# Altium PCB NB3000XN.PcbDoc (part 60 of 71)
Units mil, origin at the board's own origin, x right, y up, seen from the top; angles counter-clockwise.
Board outline 9527.56 x 6929.77 mil, 6 copper layers (Top Layer, GND+SHIELD, MidLayer1, MidLayer2, P2 - 3V3+5V0, Bottom Layer), stack 62.375 mil thick; 832 components, 1027 nets, 4655 pads, 4981 vias.
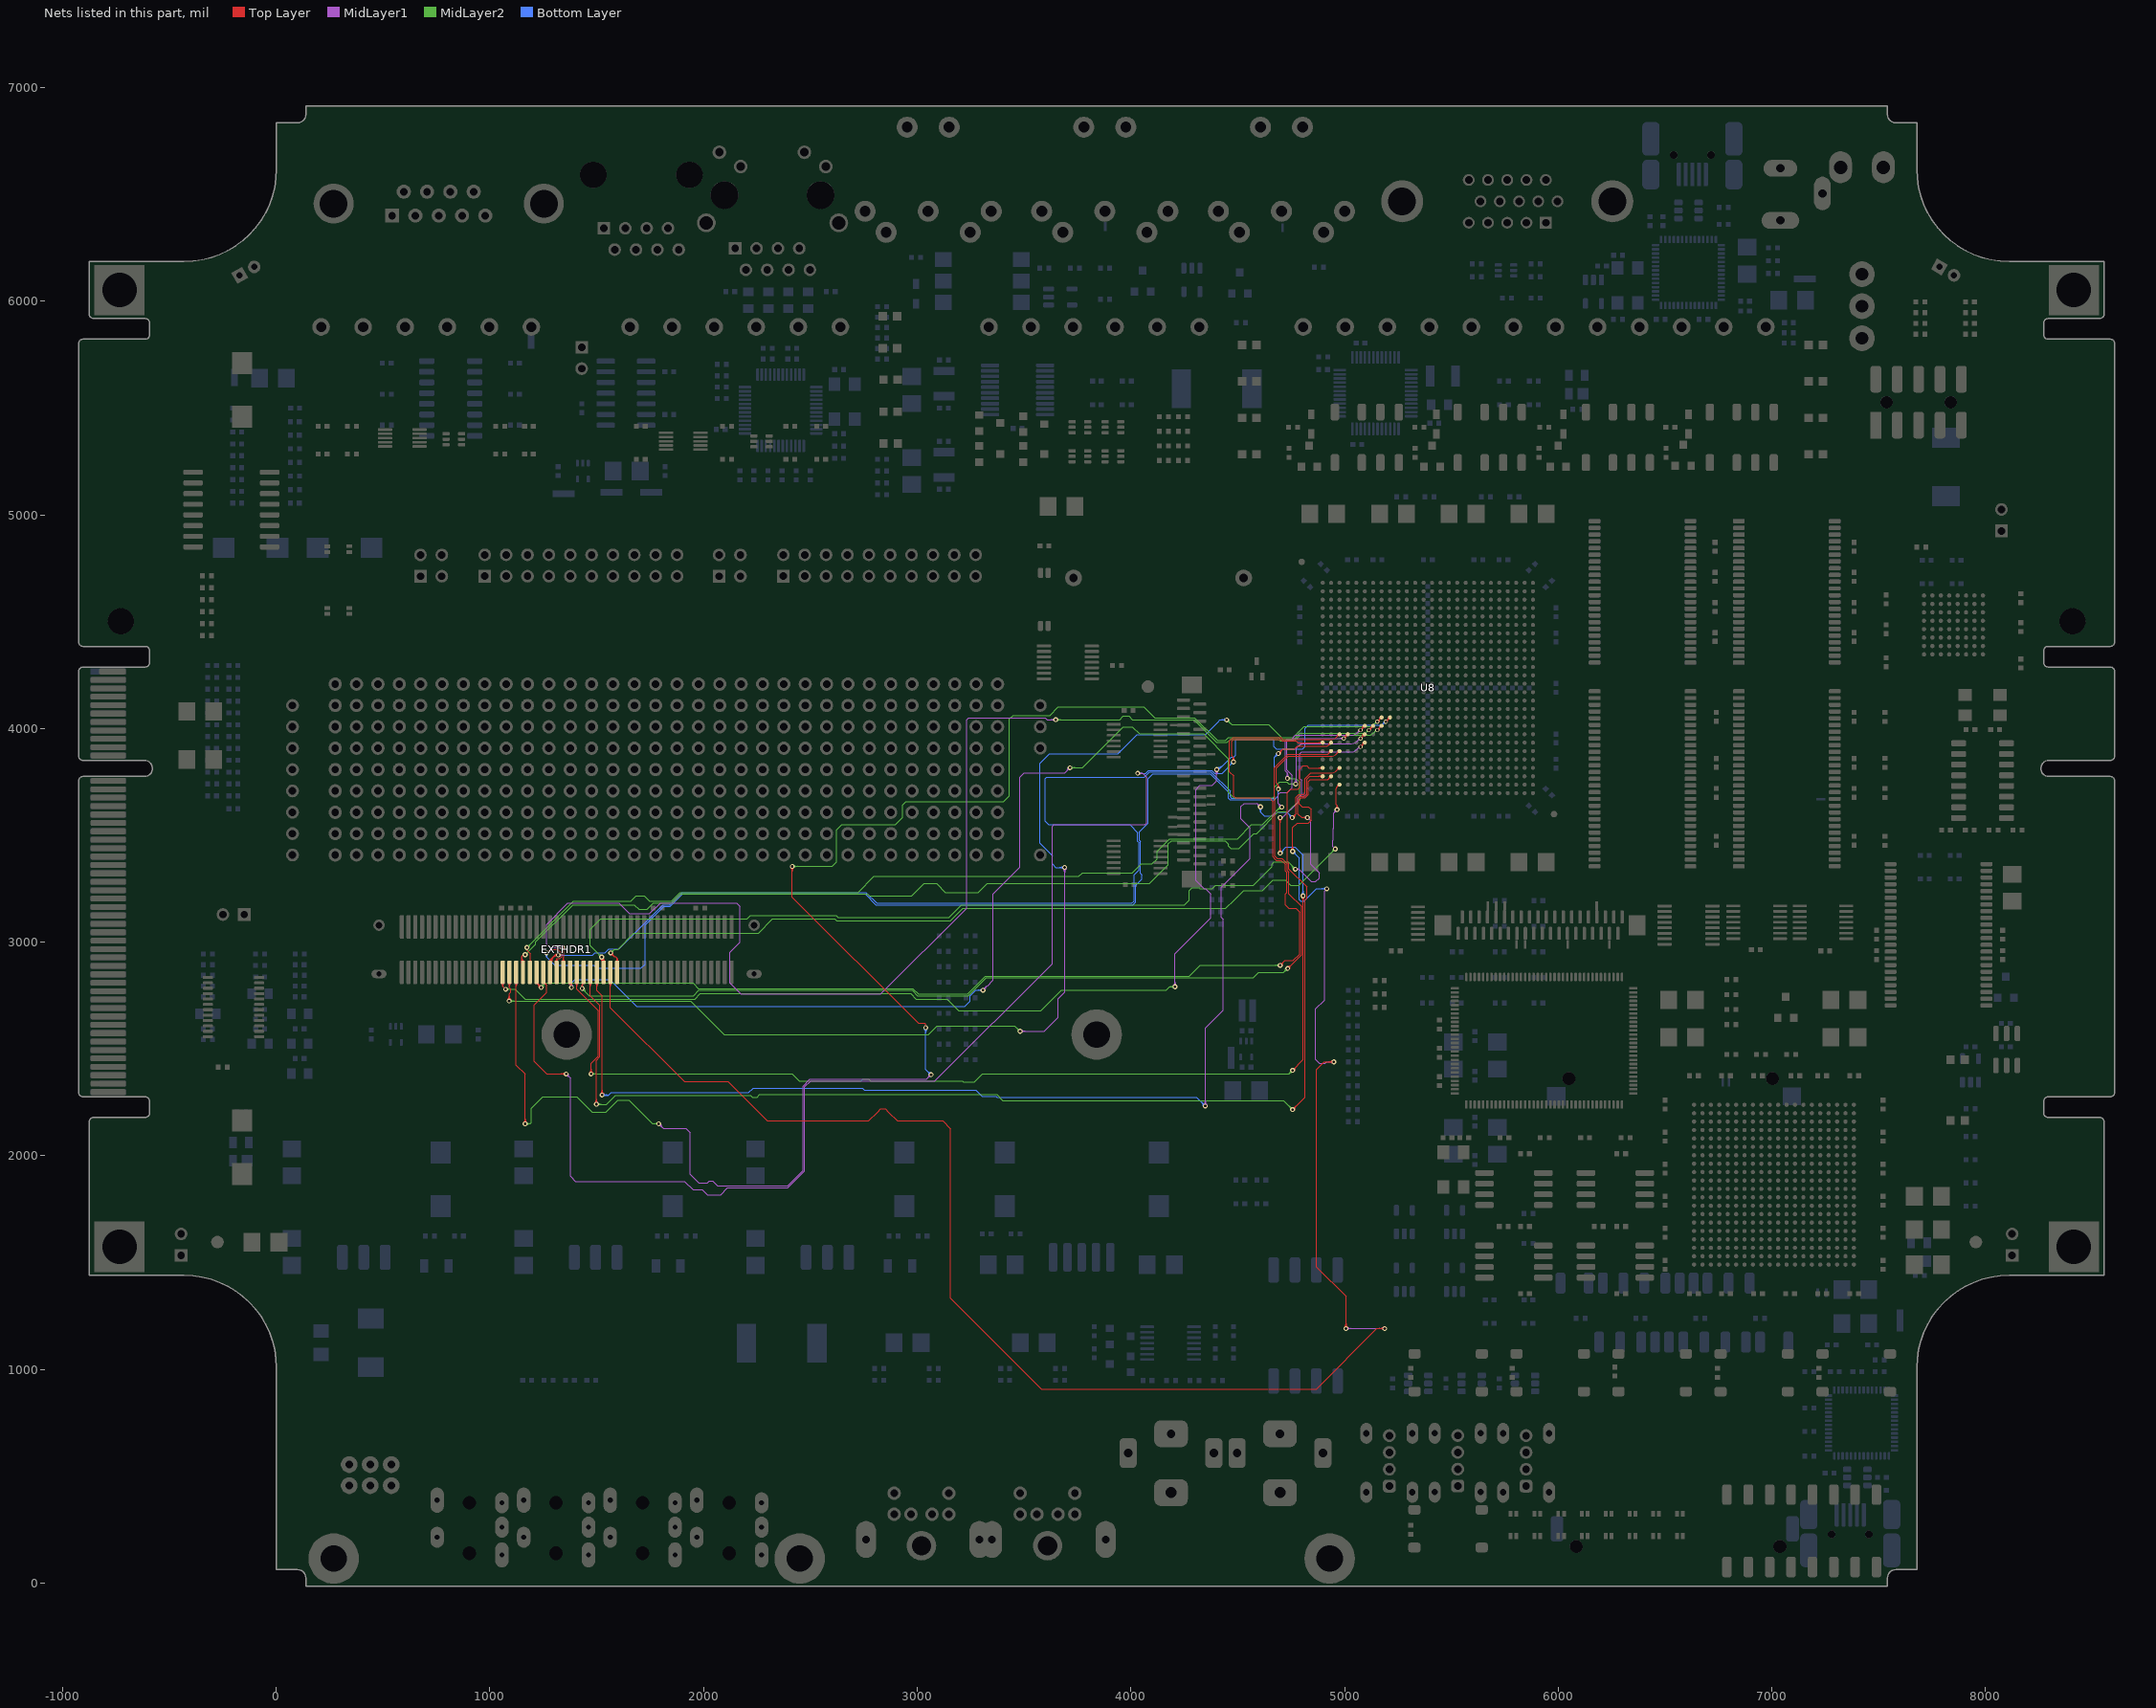
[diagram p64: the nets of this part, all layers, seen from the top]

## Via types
v1: diameter 23, hole 11.81, Top Layer to Bottom Layer, 3672 vias
v2: diameter 26, hole 11.81, Top Layer to Bottom Layer, 461 vias
v3: diameter 19, hole 11.81, Top Layer to Bottom Layer, tented both sides, 396 vias
v4: diameter 23.62, hole 11.81, Top Layer to Bottom Layer, 288 vias
v5: diameter 20, hole 11.81, Top Layer to Bottom Layer, 91 vias
v6: diameter 23, hole 11.81, Top Layer to Bottom Layer, tented both sides, 50 vias
v7: diameter 31, hole 11.81, Top Layer to Bottom Layer, 15 vias
v8: diameter 27.56, hole 11.81, Top Layer to Bottom Layer, tented both sides, 4 vias
v9: diameter 29, hole 11.81, Top Layer to Bottom Layer, 3 vias
v10: diameter 21, hole 11.81, Top Layer to Bottom Layer, 1 vias

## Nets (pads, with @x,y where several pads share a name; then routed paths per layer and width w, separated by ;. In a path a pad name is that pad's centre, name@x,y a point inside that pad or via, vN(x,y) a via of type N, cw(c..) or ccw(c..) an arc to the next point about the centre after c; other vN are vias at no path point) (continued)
PBIO.D17: EXTHDR1.36 U8.AE3 | length 4379.4
  Top Layer w4: v1@1565.19,2940.54 cw(c1565.19,2917.61) 1581.41,2933.82 cw(c1597.63,2950.04) v1@1574.69,2950.04 ; v1@1565.19,2944.54 cw(c1565.19,2931.26) 1574.58,2940.65 cw(c1583.97,2950.04) v1@1570.69,2950.04 ; v1(1565.19,2950.04) 1581.86,2933.37 1587.89,2933.37 1595.89,2925.37 EXTHDR1.36@1595.89,2859.25 ; EXTHDR1.36@1590.23,2910.03 ccw(c1576.57,2923.68) 1595.89,2923.68 ccw(c1615.2,2923.68) EXTHDR1.36@1601.55,2910.03 ; v1@4959.39,3627.9 ccw(c4950.27,3639.71) 4965.19,3639.71 ; v1(4965.19,3620.37) 4965.19,3639.71 ; v1@4970.99,3627.9 cw(c4980.11,3639.71) 4965.19,3639.71 ; 4961.11,3717.53 cw(c4971.26,3717.53) 4964.08,3724.71 ; 4961.11,3717.53 cw(c4971.26,3717.53) 4964.08,3724.71 ; 4961.11,3717.53 4961.11,3670 4961.11,3660 4961.11,3643.71 4962.44,3642.37 4962.52,3642.37 4965.19,3639.71 ; 4964.08,3724.71 cw(c4976.61,3712.17) 4976.61,3729.9 ccw(c4976.61,3712.17) 4964.08,3724.71 ; 4964.08,3724.71 ccw(c4951.55,3737.24) 4969.27,3737.24 cw(c4951.55,3737.24) 4964.08,3724.71
  MidLayer1 w4: v1@4955.69,3620.37 cw(c4932.76,3620.37) 4948.97,3604.16 cw(c4965.19,3587.94) v1@4965.19,3610.87 ; v1(4956.86,3436.71) 4945,3448.56 4945,3477.48 4947.52,3480 4947.52,3532.37 4948.52,3533.37 4948.52,3603.71 v1(4965.19,3620.37) ; v1@4959.69,3620.37 cw(c4946.41,3620.37) 4955.8,3610.99 cw(c4965.19,3601.6) v1@4965.19,3614.87
  MidLayer2 w4: v1(1565.19,2950.04) 1581.86,2966.71 1598.52,2966.71 1673.52,3041.71 2256.86,3041.71 2323.86,3108.71 2614.25,3108.71 2622.58,3100.37 3154.82,3100.37 3213.15,3158.71 4444.52,3158.71 4485.26,3199.44 4519.19,3233.37 4527.86,3242.04 4616.86,3242.04 4636.33,3261.52 4665.19,3290.37 4723.52,3290.37 4747.19,3266.71 4786.86,3266.71 v1(4956.86,3436.71) ; v1@1565.19,2955.54 ccw(c1565.19,2968.82) 1574.58,2959.43 ccw(c1583.97,2950.04) v1@1570.69,2950.04 ; v1@1565.19,2959.54 ccw(c1565.19,2982.48) 1581.41,2966.26 ccw(c1597.63,2950.04) v1@1574.69,2950.04 ; v1@4947.36,3436.71 cw(c4924.42,3436.71) 4940.64,3420.49 cw(c4956.86,3404.27) v1@4956.86,3427.21 ; v1@4951.36,3436.71 cw(c4938.08,3436.71) 4947.47,3427.32 cw(c4956.86,3417.93) v1@4956.86,3431.21
PBIO.D18: EXTHDR1.38 U8.AD2 | length 9271.8
  Top Layer w4: EXTHDR1.38@1558.74,2808.48 cw(c1545.08,2794.82) 1564.39,2794.82 cw(c1583.71,2794.82) EXTHDR1.38@1570.05,2808.48 ; EXTHDR1.38@1564.39,2859.25 1564.39,2692.51 ; 1614.73,2642.17 1564.39,2692.51 ; 2127.29,2334.02 2114.31,2347 ; v1@4750.14,3431.76 ccw(c4733.92,3447.98) 4756.86,3447.98 ccw(c4779.79,3447.98) v1@4763.57,3431.76 ; v1@4752.97,3428.93 ccw(c4743.58,3438.32) 4756.86,3438.32 ccw(c4770.14,3438.32) v1@4760.75,3428.93 ; v1(4756.86,3425.04) 4756.86,3536.86 4778.37,3558.37 4831.86,3558.37 4843.86,3570.37 4843.86,3621.37 4831.86,3633.37 4802.52,3633.37 4789.19,3646.71 4789.19,3666.71 4797.52,3675.04 4815.19,3675.04 4831.86,3691.71 4831.86,3753.17 4839.79,3761.11 4855.26,3761.11 4860,3761.11 4870,3761.11 4917.53,3761.11 ; v1@4943.28,2433.28 ccw(c4927.06,2417.06) 4927.06,2440 ccw(c4927.06,2462.93) v1@4943.28,2446.72 ; v1@4946.11,2436.11 ccw(c4936.72,2426.72) 4936.72,2440 ccw(c4936.72,2453.28) v1@4946.11,2443.89 ; v1(4950,2440) 4905,2440 4870,2405 4870,1480.19 5006.86,1343.33 v1(5006.86,1191.71) ; v1@5000.14,1198.43 ccw(c4983.92,1214.64) 5006.86,1214.64 ccw(c5029.79,1214.64) v1@5013.57,1198.43 ; v1@5002.97,1195.6 ccw(c4993.58,1204.99) 5006.86,1204.99 ccw(c5020.14,1204.99) v1@5010.75,1195.6 ; v1@5181.57,1184.99 ccw(c5165.36,1168.77) 5165.36,1191.71 ccw(c5165.36,1214.64) v1@5181.57,1198.43 ; v1@5184.4,1187.82 ccw(c5175.01,1178.43) 5175.01,1191.71 ccw(c5175.01,1204.99) v1@5184.4,1195.6 ; v1(5188.29,1191.71) 5151.71,1191.71 4868.37,908.37 3581.86,908.37 3156.86,1333.37 3156.86,2126.83 3119.69,2164 2907.06,2164 2865.5,2205.56 2850.56,2220.5 2829.44,2220.5 2814.5,2205.56 2772.94,2164 2297.31,2164 2114.31,2347 ; 1564.39,2692.51 1909.9,2347 2114.31,2347 ; 4917.53,3761.11 ccw(c4917.53,3771.26) 4924.71,3764.08 ; 4917.53,3761.11 ccw(c4917.53,3771.26) 4924.71,3764.08 ; 4924.71,3764.08 ccw(c4912.17,3776.61) 4929.9,3776.61 cw(c4912.17,3776.61) 4924.71,3764.08 ; 4924.71,3764.08 cw(c4937.24,3751.55) 4937.24,3769.27 ccw(c4937.24,3751.55) 4924.71,3764.08
  MidLayer1 w4: v1(4916.86,3250.04) 4906.86,3240.04 4906.86,2755 4906.86,2729.06 4865.19,2687.39 4865.19,2683.37 4865.19,2669 4865.19,2450.04 4881.86,2433.37 4910,2433.37 4916.63,2440 v1(4950,2440) ; v1@4943.28,2433.28 ccw(c4927.06,2417.06) 4927.06,2440 ccw(c4927.06,2462.93) v1@4943.28,2446.72 ; v1@4946.11,2436.11 ccw(c4936.72,2426.72) 4936.72,2440 ccw(c4936.72,2453.28) v1@4946.11,2443.89 ; v1(5006.86,1191.71) v1(5188.29,1191.71) ; v1@5010.75,1187.82 cw(c5020.14,1178.43) 5020.14,1191.71 cw(c5020.14,1204.99) v1@5010.75,1195.6 ; v1@5013.57,1184.99 cw(c5029.79,1168.77) 5029.79,1191.71 cw(c5029.79,1214.64) v1@5013.57,1198.43 ; v1@5181.57,1184.99 ccw(c5165.36,1168.77) 5165.36,1191.71 ccw(c5165.36,1214.64) v1@5181.57,1198.43 ; v1@5184.4,1187.82 ccw(c5175.01,1178.43) 5175.01,1191.71 ccw(c5175.01,1204.99) v1@5184.4,1195.6
  Bottom Layer w4: v1@4756.86,3415.54 cw(c4756.86,3392.61) 4773.07,3408.82 cw(c4789.29,3425.04) v1@4766.36,3425.04 ; v1@4756.86,3419.54 cw(c4756.86,3406.26) 4766.25,3415.65 cw(c4775.64,3425.04) v1@4762.36,3425.04 ; v1(4756.86,3425.04) 4787.86,3394.04 4787.86,3198.04 4794.19,3191.71 4811.19,3191.71 4869.52,3250.04 v1(4916.86,3250.04) ; v1@4910.14,3243.32 ccw(c4893.92,3227.11) 4893.92,3250.04 ccw(c4893.92,3272.98) v1@4910.14,3256.76 ; v1@4912.97,3246.15 ccw(c4903.58,3236.76) 4903.58,3250.04 ccw(c4903.58,3263.32) v1@4912.97,3253.93
PBIO.D19: EXTHDR1.40 U8.AD1 | length 4887.7
  Top Layer w4: v1@1516.81,2923.66 cw(c1477.96,2884.81) EXTHDR1.40@1532.9,2884.81 ; v1@1519.64,2926.49 cw(c1487.62,2894.47) EXTHDR1.40@1532.9,2894.47 ; v1@1522.46,2929.31 cw(c1497.27,2904.13) EXTHDR1.40@1532.9,2904.13 ; v1(1523.52,2930.37) 1532.9,2921 ; v1@1525.29,2932.14 cw(c1506.93,2913.78) EXTHDR1.40@1532.9,2913.78 ; EXTHDR1.40@1527.9,2910.62 ccw(c1519.61,2921) 1532.9,2921 ; EXTHDR1.40@1532.9,2859.25 1532.9,2921 ; EXTHDR1.40@1537.89,2910.62 cw(c1546.19,2921) 1532.9,2921 ; v1@4819.47,3576.66 ccw(c4803.26,3560.44) 4803.26,3583.37 ccw(c4803.26,3606.31) v1@4819.47,3590.09 ; v1@4822.3,3579.49 ccw(c4812.91,3570.1) 4812.91,3583.37 ccw(c4812.91,3596.65) v1@4822.3,3587.26 ; v1(4826.19,3583.37) 4798.52,3583.37 4781.19,3600.71 4781.19,3674.23 4790,3683.04 4811.88,3683.04 4823.52,3694.69 4823.52,3763.33 4836.81,3776.61 4855.26,3776.61 4860,3776.61 4870,3776.61 U8.AD1@4897.87,3776.61 ; U8.AD1@4892.57,3771.31 ccw(c4879.77,3758.51) 4879.77,3776.61 ccw(c4879.77,3794.72) U8.AD1@4892.57,3781.92 ; U8.AD1@4892.68,3771.42 ccw(c4880.15,3758.89) 4880.15,3776.61 ccw(c4880.15,3794.34) U8.AD1@4892.68,3781.81
  MidLayer1 w4: v1(4769.86,3341.71) 4786.52,3341.71 ; v1@4778.03,3336.87 cw(c4786.52,3331.84) 4786.52,3341.71 ; v1@4778.03,3346.55 ccw(c4786.52,3351.58) 4786.52,3341.71 ; v1(4826.19,3583.37) 4841.19,3568.37 4841.19,3365.71 4881.86,3325.04 4881.86,3300.04 4865.19,3283.37 4844.86,3283.37 4786.52,3341.71
  MidLayer2 w4: v1@1514.02,2930.37 ccw(c1491.09,2930.37) 1507.31,2946.59 ccw(c1523.52,2962.81) v1@1523.52,2939.87 ; v1@1518.02,2930.37 ccw(c1504.75,2930.37) 1514.14,2939.76 ccw(c1523.52,2949.15) v1@1523.52,2935.87 ; v1(1523.52,2930.37) 1470,2983.9 1470,3060.2 1518.17,3108.37 2203.88,3108.37 2220.54,3125.04 2620.54,3125.04 2628.88,3116.71 3148.52,3116.71 3206.86,3175.04 4251.19,3175.04 4273.52,3197.37 4273.52,3242.71 4285.82,3255 4319.9,3255 4323.52,3251.37 4381.86,3251.37 4397.19,3266.71 4574.21,3266.71 4660,3352.5 4660,3365.04 4670,3375.04 4736.52,3375.04 v1(4769.86,3341.71) ; v1@4760.36,3341.71 ccw(c4737.42,3341.71) 4753.64,3357.93 ccw(c4769.86,3374.14) v1@4769.86,3351.21 ; v1@4764.36,3341.71 ccw(c4751.08,3341.71) 4760.47,3351.1 ccw(c4769.86,3360.49) v1@4769.86,3347.21
PBIO.D20: EXTHDR1.42 U8.AC3 | length 6337.2
  Top Layer w4: EXTHDR1.42@1495.74,2808.48 cw(c1482.09,2794.82) 1501.4,2794.82 cw(c1520.71,2794.82) EXTHDR1.42@1507.06,2808.48 ; EXTHDR1.42@1501.4,2859.25 1501.4,2773.6 1525,2750 v1(1525,2285) ; v1@1518.28,2291.72 ccw(c1502.06,2307.93) 1525,2307.93 ccw(c1547.93,2307.93) v1@1531.72,2291.72 ; v1@1521.11,2288.89 ccw(c1511.72,2298.28) 1525,2298.28 ccw(c1538.28,2298.28) v1@1528.89,2288.89 ; v1(4755.52,3583.37) 4772.86,3600.71 4772.86,3677.86 4786.04,3691.04 4808.56,3691.04 4815.19,3697.67 4815.19,3766.31 4841,3792.12 4860,3792.12 4870,3792.12 4936.73,3792.12 ; v1@4755.52,3588.87 ccw(c4755.52,3602.15) 4764.91,3592.76 ccw(c4774.3,3583.37) v1@4761.02,3583.37 ; v1@4755.52,3592.87 ccw(c4755.52,3615.81) 4771.74,3599.59 ccw(c4787.96,3583.37) v1@4765.02,3583.37 ; 4936.73,3792.12 ccw(c4936.73,3830.8) 4964.08,3803.45 cw(c4936.73,3830.8) 4936.73,3792.12 ; 4964.08,3803.45 cw(c4976.61,3790.92) 4976.61,3808.64 ccw(c4976.61,3790.92) 4964.08,3803.45 ; 4964.08,3803.45 ccw(c4951.55,3815.98) 4969.27,3815.98 cw(c4951.55,3815.98) 4964.08,3803.45
  MidLayer1 w4: v1@4341.81,2240.09 ccw(c4325.59,2256.31) 4348.52,2256.31 ccw(c4371.46,2256.31) v1@4355.24,2240.09 ; v1@4344.64,2237.26 ccw(c4335.25,2246.65) 4348.52,2246.65 ccw(c4361.8,2246.65) v1@4352.41,2237.26 ; v1(4348.52,2233.37) 4348.52,2599.43 4431.86,2682.77 4431.86,3107.08 4423.52,3115.42 4423.52,3258.37 4556.86,3391.71 4556.86,3536.04 4515.19,3577.71 4515.19,3635.19 4530,3650 4590.23,3650 v1(4606.86,3633.37) v1@4598.52,3633.37 ; v1@4597.36,3633.37 ccw(c4574.42,3633.37) 4590.64,3649.59 ccw(c4606.86,3665.81) v1@4606.86,3642.87 ; v1@4601.36,3633.37 ccw(c4588.08,3633.37) 4597.47,3642.76 ccw(c4606.86,3652.15) v1@4606.86,3638.87
  Bottom Layer w4: v1@1528.89,2281.11 cw(c1538.28,2271.72) 1538.28,2285 cw(c1538.28,2298.28) 1528.89,2288.89 ccw(c1542.2,2302.2) 1542.2,2283.37 ; 1544.01,2283.37 ccw(c1544.01,2265.99) 1531.72,2278.28 cw(c1547.93,2262.06) 1547.93,2285 cw(c1547.93,2307.93) 1531.72,2291.72 ccw(c1551.86,2311.86) 1551.86,2283.37 ; v1@4339.02,2233.37 ccw(c4316.09,2233.37) 4332.31,2249.59 ccw(c4348.52,2265.81) v1@4348.52,2242.87 ; v1@4342.65,2227.5 v1(4348.52,2233.37) 4307.02,2274.87 3372.5,2274.87 3368.88,2278.5 3304.39,2278.5 3275.39,2307.5 2752.75,2307.5 2742.75,2317.5 2232.75,2317.5 2211.27,2296.02 1567.65,2296.02 1556.63,2285 ; v1@4343.02,2233.37 ccw(c4329.75,2233.37) 4339.14,2242.76 ccw(c4348.52,2252.15) v1@4348.52,2238.87 ; v1@4600.14,3626.66 cw(c4583.92,3610.44) 4606.86,3610.44 cw(c4629.79,3610.44) v1@4613.57,3626.66 ; v1@4602.97,3629.49 cw(c4593.58,3620.1) 4606.86,3620.1 cw(c4620.14,3620.1) v1@4610.75,3629.49 ; v1(4606.86,3633.37) 4606.86,3608.14 4625,3590 4660,3590 4678.37,3608.37 4730.52,3608.37 v1(4755.52,3583.37) v1@4765.19,3583.37 ; v1@4746.02,3583.37 ccw(c4723.09,3583.37) 4739.31,3599.59 ccw(c4755.52,3615.81) v1@4755.52,3592.87 ; v1@4750.02,3583.37 ccw(c4736.75,3583.37) 4746.14,3592.76 ccw(c4755.52,3602.15) v1@4755.52,3588.87 ; 1556.63,2285 v1(1525,2285) 1526.63,2283.37 1555,2283.37 1556.63,2285
PBIO.D21: EXTHDR1.44 U8.AC1 | length 6090
  Top Layer w4: EXTHDR1.44@1464.25,2808.48 cw(c1450.59,2794.82) 1469.9,2794.82 cw(c1489.22,2794.82) EXTHDR1.44@1475.56,2808.48 ; EXTHDR1.44@1469.9,2859.25 1469.9,2750 1515.19,2704.71 1515.19,2463.73 1498.52,2447.06 v1(1498.52,2241.71) ; v1@1491.81,2248.43 ccw(c1475.59,2264.64) 1498.52,2264.64 ccw(c1521.46,2264.64) v1@1505.24,2248.43 ; v1@1494.64,2245.6 ccw(c1485.25,2254.99) 1498.52,2254.99 ccw(c1511.8,2254.99) v1@1502.41,2245.6 ; v1(4756.86,2216.71) 4814.86,2274.71 4814.86,3196.33 4823.52,3205 4823.52,3259.37 4740.19,3342.71 4740.19,3369.69 4732.19,3377.69 4732.19,3700.37 4748.52,3716.71 4781.86,3716.71 4790.19,3725.04 4790.19,3808.37 4806.86,3825.04 4824.96,3825.04 4834.01,3815.99 4851.26,3815.99 4855.26,3815.98 4860,3815.98 4870,3815.98 U8.AC1@4897.87,3815.98 ; v1@4756.86,2222.21 ccw(c4756.86,2235.49) 4766.25,2226.1 ccw(c4775.64,2216.71) v1@4762.36,2216.71 ; v1@4756.86,2226.21 ccw(c4756.86,2249.14) 4773.07,2232.93 ccw(c4789.29,2216.71) v1@4766.36,2216.71 ; U8.AC1@4892.57,3810.68 ccw(c4879.77,3797.88) 4879.77,3815.98 ccw(c4879.77,3834.09) U8.AC1@4892.57,3821.29 ; U8.AC1@4892.68,3810.79 ccw(c4880.15,3798.26) 4880.15,3815.98 ccw(c4880.15,3833.71) U8.AC1@4892.68,3821.18
  MidLayer2 w4: v1(1498.52,2241.71) 1546.31,2241.71 1588.61,2284 2219.94,2284 2229.44,2274.5 2250.56,2274.5 2262.56,2286.5 3372.19,2286.5 3399.98,2258.71 4714.86,2258.71 v1(4756.86,2216.71) ; v1@1502.41,2237.82 cw(c1511.8,2228.43) 1511.8,2241.71 cw(c1511.8,2254.99) v1@1502.41,2245.6 ; v1@1505.24,2234.99 cw(c1521.46,2218.77) 1521.46,2241.71 cw(c1521.46,2264.64) v1@1505.24,2248.43 ; v1@4747.36,2216.71 ccw(c4724.42,2216.71) 4740.64,2232.93 ccw(c4756.86,2249.14) v1@4756.86,2226.21 ; v1@4751.36,2216.71 ccw(c4738.08,2216.71) 4747.47,2226.1 ccw(c4756.86,2235.49) v1@4756.86,2222.21
PBIO.D22: EXTHDR1.46 U8.AA2 | length 5033.5
  Top Layer w4: v1@1427.03,2791.56 ccw(c1422.06,2800) 1431.86,2800 ccw(c1441.65,2800) v1@1436.68,2791.56 ; v1(1431.86,2783.37) 1431.86,2800 1438.41,2806.55 EXTHDR1.46@1438.41,2859.25 ; v1(4733.86,2877.04) 4798.52,2941.71 4798.52,3166.71 4739.19,3226.04 4739.19,3329.02 4731.86,3336.36 4731.86,3366.71 4706.86,3391.71 4684.84,3391.71 4673.52,3403.02 4673.52,3682.37 4672.52,3683.37 4672.52,3817.52 4734.22,3879.22 4860,3879.22 4870,3879.22 4917.53,3879.22 ; v1@4733.86,2882.54 ccw(c4733.86,2895.82) 4743.25,2886.43 ccw(c4752.64,2877.04) v1@4739.36,2877.04 ; v1@4733.86,2886.54 ccw(c4733.86,2909.48) 4750.07,2893.26 ccw(c4766.29,2877.04) v1@4743.36,2877.04 ; 4917.53,3879.22 ccw(c4917.53,3889.37) 4924.71,3882.19 ; 4917.53,3879.22 ccw(c4917.53,3889.37) 4924.71,3882.19 ; 4924.71,3882.19 ccw(c4912.17,3894.72) 4929.9,3894.72 cw(c4912.17,3894.72) 4924.71,3882.19 ; 4924.71,3882.19 cw(c4937.24,3869.66) 4937.24,3887.38 ccw(c4937.24,3869.66) 4924.71,3882.19
  MidLayer2 w4: v1@1431.86,2773.87 cw(c1431.86,2750.94) 1448.07,2767.16 cw(c1464.29,2783.37) v1@1441.36,2783.37 ; v1@1431.86,2777.87 cw(c1431.86,2764.6) 1441.25,2773.99 cw(c1450.64,2783.37) v1@1437.36,2783.37 ; v1(1431.86,2783.37) 1465.19,2750.04 1935,2750.04 1950,2750.04 1953.35,2750.04 1978.69,2775.37 2010,2775.37 2976.33,2775.37 3001.67,2750.04 3239.52,2750.04 3322.86,2833.37 4573.52,2833.37 4598.52,2858.37 4715.19,2858.37 v1(4733.86,2877.04) ; v1@4724.36,2877.04 cw(c4701.42,2877.04) 4717.64,2860.82 cw(c4733.86,2844.61) v1@4733.86,2867.54 ; v1@4728.36,2877.04 cw(c4715.08,2877.04) 4724.47,2867.65 cw(c4733.86,2858.26) v1@4733.86,2871.54
PBIO.D23: EXTHDR1.48 U8.Y6 | length 6533
  Top Layer w4: EXTHDR1.48@1401.26,2808.48 cw(c1387.73,2794.95) 1406.86,2794.95 ; 1406.86,2794.69 cw(c1426.36,2794.69) EXTHDR1.48@1412.57,2808.48 ; EXTHDR1.48@1406.86,2859.25 1406.86,2780 1506.86,2680 1506.86,2627.37 1506.86,2625 1506.86,2466.71 1473.52,2433.37 v1(1473.52,2383.37) ; v1@1466.81,2390.09 ccw(c1450.59,2406.31) 1473.52,2406.31 ccw(c1496.46,2406.31) v1@1480.24,2390.09 ; v1@1469.64,2387.26 ccw(c1460.25,2396.65) 1473.52,2396.65 ccw(c1486.8,2396.65) v1@1477.41,2387.26 ; v1@4691.81,3423.43 ccw(c4675.59,3439.64) 4698.52,3439.64 ccw(c4721.46,3439.64) v1@4705.24,3423.43 ; v1@4691.81,3576.66 cw(c4675.59,3560.44) 4698.52,3560.44 cw(c4721.46,3560.44) v1@4705.24,3576.66 ; v1@4694.64,3420.6 ccw(c4685.25,3429.99) 4698.52,3429.99 ccw(c4711.8,3429.99) v1@4702.41,3420.6 ; v1@4694.64,3579.49 cw(c4685.25,3570.1) 4698.52,3570.1 cw(c4711.8,3570.1) v1@4702.41,3579.49 ; v1(4698.52,3416.71) v1(4698.52,3583.37) ; v1(4756.86,2400.04) 4806.86,2450.04 4806.86,3215.37 v1(4805.52,3216.71) ; v1@4756.86,2405.54 ccw(c4756.86,2418.82) 4766.25,2409.43 ccw(c4775.64,2400.04) v1@4762.36,2400.04 ; v1@4756.86,2409.54 ccw(c4756.86,2432.48) 4773.07,2416.26 ccw(c4789.29,2400.04) v1@4766.36,2400.04 ; v1@4798.81,3209.99 cw(c4779.37,3190.55) 4806.86,3190.55 ; v1@4801.64,3212.82 cw(c4789.03,3200.21) 4806.86,3200.21 ; 4806.86,3196.99 cw(c4825.24,3196.99) v1@4812.24,3209.99 ; v3(5075.04,3914.41) U8.Y6@5094.72,3934.09 ; U8.Y6@5087.22,3934.09 cw(c5069.12,3934.09) 5081.92,3921.29 cw(c5094.72,3908.49) U8.Y6@5094.72,3926.59 ; U8.Y6@5087.38,3934.09 cw(c5069.66,3934.09) 5082.19,3921.56 cw(c5094.72,3909.03) U8.Y6@5094.72,3926.75 ; 5087.84,3927.21 cw(c5075.04,3940.02) 5075.04,3921.91 ccw(c5075.04,3940.02) 5087.84,3927.21 ; 5087.84,3927.21 ccw(c5100.65,3914.41) 5082.54,3914.41 cw(c5100.65,3914.41) 5087.84,3927.21
  MidLayer1 w4: v1(4698.52,3583.37) 4710.86,3583.37 4781.86,3654.37 4781.86,3675.04 4798.52,3691.71 4798.52,3759.71 4791.52,3766.71 4791.52,3881.52 4800.55,3890.55 4860,3890.55 4870,3890.55 4918.62,3890.55 4938.04,3890.55 5012.16,3890.55 ; 4998.23,3890.55 5012.16,3890.55 ; v3@5067.65,3915.71 cw(c5049.82,3918.86) 5060.21,3904.02 ; v3@5073.74,3907.02 ccw(c5070.59,3889.19) 5060.21,3904.02 ; 5012.16,3890.55 5035.41,3890.55 ; 5035.41,3890.55 ccw(c5035.41,3914.32) 5035.58,3890.55 ; 5035.41,3890.55 5035.58,3890.55 ; 5035.58,3890.55 ccw(c5035.41,3914.32) 5051.63,3896.94 5060.21,3904.02
  MidLayer2 w4: v1(1473.52,2383.37) 2414,2383.37 2447.34,2350.04 2737.66,2350.04 2746.12,2358.5 2773.88,2358.5 2782.34,2350.04 3211.19,2350.04 3215.19,2346.04 3267.67,2346.04 3305,2383.37 4740.19,2383.37 v1(4756.86,2400.04) ; v1@1477.41,2379.49 cw(c1486.8,2370.1) 1486.8,2383.37 cw(c1486.8,2396.65) v1@1477.41,2387.26 ; v1@1480.24,2376.66 cw(c1496.46,2360.44) 1496.46,2383.37 cw(c1496.46,2406.31) v1@1480.24,2390.09 ; v1@4747.36,2400.04 cw(c4724.42,2400.04) 4740.64,2383.82 cw(c4756.86,2367.61) v1@4756.86,2390.54 ; v1@4751.36,2400.04 cw(c4738.08,2400.04) 4747.47,2390.65 cw(c4756.86,2381.26) v1@4756.86,2394.54
  Bottom Layer w4: v1(4698.52,3416.71) 4726.19,3444.37 4767.52,3444.37 4805.52,3406.37 v1(4805.52,3216.71) ; v1@4698.52,3422.21 ccw(c4698.52,3435.49) 4707.91,3426.1 ccw(c4717.3,3416.71) v1@4704.02,3416.71 ; v1@4698.52,3426.21 ccw(c4698.52,3449.14) 4714.74,3432.93 ccw(c4730.96,3416.71) v1@4708.02,3416.71 ; v1@4798.81,3223.43 ccw(c4782.59,3239.64) 4805.52,3239.64 ccw(c4828.46,3239.64) v1@4812.24,3223.43 ; v1@4801.64,3220.6 ccw(c4792.25,3229.99) 4805.52,3229.99 ccw(c4818.8,3229.99) v1@4809.41,3220.6
PBIO.D24: EXTHDR1.50 U8.W6 | length 5998.1
  Top Layer w4: EXTHDR1.50@1371.07,2807.42 cw(c1358.23,2787.58) v1@1381.86,2787.58 ; EXTHDR1.50@1373.24,2810.77 cw(c1362.99,2794.94) v1@1381.86,2794.94 ; EXTHDR1.50@1375.42,2814.13 cw(c1367.75,2802.29) 1381.86,2802.29 ; EXTHDR1.50@1375.42,2859.25 1375.42,2811.44 1381.86,2805 v1(1381.86,2788.37) ; v1@1377.03,2796.56 ccw(c1372.06,2805) 1381.86,2805 ccw(c1391.65,2805) v1@1386.68,2796.56 ; v3(5075.04,3953.78) U8.W6@5094.72,3973.46 ; U8.W6@5087.22,3973.46 cw(c5069.12,3973.46) 5081.92,3960.66 cw(c5094.72,3947.86) U8.W6@5094.72,3965.96 ; U8.W6@5087.38,3973.46 cw(c5069.66,3973.46) 5082.19,3960.93 cw(c5094.72,3948.4) U8.W6@5094.72,3966.12 ; 5087.84,3966.58 ccw(c5100.65,3953.78) 5082.54,3953.78 cw(c5100.65,3953.78) 5087.84,3966.58 ; 5087.84,3966.58 cw(c5075.04,3979.39) 5075.04,3961.28 ccw(c5075.04,3979.39) 5087.84,3966.58
  MidLayer1 w4: v1(3307.86,2775.04) 3311.19,2775.04 3315.19,2779.04 3315.19,2783.37 3326.71,2794.9 ; v1@3307.86,2780.54 ccw(c3307.86,2791.4) 3315.54,2783.72 ; v1@3307.86,2784.54 ccw(c3307.86,2805.06) 3322.37,2790.55 ; v1@3313.36,2775.04 cw(c3329.05,2775.04) 3317.95,2786.14 ; v1@3317.36,2775.04 cw(c3342.71,2775.04) 3324.78,2792.97 ; 3327.21,2794.4 3355,2822.18 3355,3225 3481.52,3351.52 3481.52,3771.73 3501.5,3791.71 3690.19,3791.71 v1(3715.19,3816.71) ; v1@3705.69,3816.71 cw(c3682.76,3816.71) 3698.97,3800.49 cw(c3715.19,3784.27) v1@3715.19,3807.21 ; v1@3709.69,3816.71 cw(c3696.41,3816.71) 3705.8,3807.32 cw(c3715.19,3797.93) v1@3715.19,3811.21 ; v1@4765.14,3747.09 ccw(c4740.88,3771.36) 4775.19,3771.36 ; v1@4767.97,3744.26 ccw(c4750.53,3761.7) 4775.19,3761.7 ; v1@4770.8,3741.44 ccw(c4760.19,3752.04) 4775.19,3752.04 ; v1(4771.86,3740.37) 4771.86,3741.71 4775.19,3745.04 4775.19,3908.37 4796.73,3929.92 4860,3929.92 4870,3929.92 4918.62,3929.92 4938.04,3929.92 5012.16,3929.92 ; 4775.19,3755.26 ccw(c4786.75,3755.26) v1@4778.57,3747.09 ; 4998.23,3929.92 5012.16,3929.92 ; v3@5067.57,3954.43 cw(c5049.53,3956.01) 5061.17,3942.14 ; v3@5074.39,3946.31 ccw(c5072.81,3928.27) 5061.17,3942.14 ; 5012.16,3929.92 5031.66,3929.92 ccw(c5031.66,3971.65) 5061.17,3942.14
  MidLayer2 w4: v1(3715.19,3816.71) 3773.52,3816.71 3965.19,4008.37 4006.86,4008.37 4040.19,3975.04 4340.19,3975.04 4456.86,3858.37 4456.86,3700.04 4481.86,3675.04 4665.19,3675.04 4672.52,3682.37 4672.52,3725.04 4696.52,3749.04 4730,3749.04 4738.67,3740.37 v1(4771.86,3740.37) ; v1@3719.08,3812.82 cw(c3728.47,3803.43) 3728.47,3816.71 cw(c3728.47,3829.99) v1@3719.08,3820.6 ; v1@3721.91,3809.99 cw(c3738.13,3793.77) 3738.13,3816.71 cw(c3738.13,3839.64) v1@3721.91,3823.43 ; v1@4765.14,3733.66 ccw(c4748.92,3717.44) 4748.92,3740.37 ccw(c4748.92,3763.31) v1@4765.14,3747.09 ; v1@4767.97,3736.49 ccw(c4758.58,3727.1) 4758.58,3740.37 ccw(c4758.58,3753.65) v1@4767.97,3744.26
  Bottom Layer w4: v1@1375.86,2795.74 ccw(c1365.56,2808.37) 1381.86,2808.37 ; v1@1378.38,2792.64 ccw(c1372.42,2799.95) 1381.86,2799.95 ccw(c1391.29,2799.95) v1@1385.33,2792.64 ; v1(1381.86,2788.37) 1381.86,2808.37 ; v1@1387.86,2795.74 cw(c1398.16,2808.37) 1381.86,2808.37 ; v1@3301.14,2768.32 ccw(c3284.92,2752.11) 3284.92,2775.04 ccw(c3284.92,2797.98) v1@3301.14,2781.76 ; v1@3303.97,2771.15 ccw(c3294.58,2761.76) 3294.58,2775.04 ccw(c3294.58,2788.32) v1@3303.97,2778.93 ; v1(3307.86,2775.04) 3273.52,2775.04 3248.52,2750.04 3248.52,2725.04 3223.52,2700.04 1687.21,2700.04 1562.21,2825.04 1398.52,2825.04 1381.86,2808.37
PBIO.D25: EXTHDR1.52 U8.V8 | length 6211.4
  Top Layer w4: EXTHDR1.52@1338.26,2910.03 ccw(c1324.61,2923.68) 1343.92,2923.68 ccw(c1363.23,2923.68) EXTHDR1.52@1349.58,2910.03 ; v1(1340.19,2975.04) 1340.19,2959.81 1345.5,2954.5 1345.5,2929.44 1343.92,2927.86 EXTHDR1.52@1343.92,2859.25 ; v3(5153.78,3993.15) U8.V8@5173.46,4012.83 ; v3@5161.28,3993.15 cw(c5179.39,3993.15) 5166.58,4005.95 ; v3@5161.28,3993.15 cw(c5179.39,3993.15) 5166.58,4005.95 ; U8.V8@5165.96,4012.83 cw(c5147.86,4012.83) 5160.66,4000.03 cw(c5173.46,3987.23) U8.V8@5173.46,4005.33 ; U8.V8@5166.12,4012.83 cw(c5148.4,4012.83) 5160.93,4000.3 cw(c5173.46,3987.77) U8.V8@5173.46,4005.49 ; 5166.58,4005.95 cw(c5153.78,4018.76) 5153.78,4000.65 ccw(c5153.78,4018.76) 5166.58,4005.95
  MidLayer1 w4: v1@1333.47,2968.32 ccw(c1317.26,2952.11) 1317.26,2975.04 ccw(c1317.26,2997.98) v1@1333.47,2981.76 ; v1@1336.3,2971.15 ccw(c1326.91,2961.76) 1326.91,2975.04 ccw(c1326.91,2988.32) v1@1336.3,2978.93 ; v1(1340.19,2975.04) 1281.86,2975.04 1265.19,2991.71 1265.19,3083.37 1365.19,3183.37 1603.88,3183.37 1653.88,3133.37 1748.17,3133.37 1798.5,3183.71 2154.98,3183.71 2170,3168.69 2170,2999.79 2123.52,2953.31 2123.52,2808.37 2174.77,2757.13 2830,2757.13 3231.86,3158.98 3231.86,4041.71 3240.19,4050.04 3600,4050.04 3608.33,4041.71 v1(3648.52,4041.71) ; v1@3641.81,4034.99 ccw(c3625.59,4018.77) 3625.59,4041.71 ccw(c3625.59,4064.64) v1@3641.81,4048.43 ; v1@3644.64,4037.82 ccw(c3635.25,4028.43) 3635.25,4041.71 ccw(c3635.25,4054.99) v1@3644.64,4045.6
  MidLayer2 w4: v1(3648.52,4041.71) 3948.52,4041.71 3965.19,4058.37 3990.19,4058.37 4006.52,4042.04 4294.86,4042.04 4303.52,4033.37 4400.86,3936.04 4451.19,3936.04 4465.19,3950.04 4690.19,3950.04 4698.52,3941.71 4765.8,3941.71 4793.38,3969.29 4860,3969.29 4870,3969.29 4997.36,3969.29 5016.78,3969.29 5090.9,3969.29 5114.15,3969.29 ccw(c5114.15,3993.06) 5130.37,3975.68 5138.95,3982.76 ; v1@3652.41,4037.82 cw(c3661.8,4028.43) 3661.8,4041.71 cw(c3661.8,4054.99) v1@3652.41,4045.6 ; v1@3655.24,4034.99 cw(c3671.46,4018.77) 3671.46,4041.71 cw(c3671.46,4064.64) v1@3655.24,4048.43 ; v3@5146.39,3994.45 cw(c5128.56,3997.6) 5138.95,3982.76 ; v3@5152.48,3985.76 ccw(c5149.33,3967.93) 5138.95,3982.76
PBIO.D26: EXTHDR1.54 U8.AA3 | length 5300.7
  Top Layer w4: v1(1265.19,2950.04) 1281.86,2966.71 1318.04,2966.71 1337.5,2947.25 1337.5,2932.75 1327.25,2922.5 1312.65,2922.5 1312.42,2922.27 ; v1@1265.19,2955.54 ccw(c1265.19,2968.82) 1274.58,2959.43 ccw(c1283.97,2950.04) v1@1270.69,2950.04 ; v1@1265.19,2959.54 ccw(c1265.19,2982.48) 1281.41,2966.26 ccw(c1297.63,2950.04) v1@1274.69,2950.04 ; EXTHDR1.54@1307.09,2910.33 ccw(c1296.39,2922.27) 1312.42,2922.27 ; EXTHDR1.54@1312.43,2904.36 EXTHDR1.54@1312.42,2859.25 1312.42,2922.27 ; EXTHDR1.54@1317.76,2910.33 cw(c1328.46,2922.27) 1312.42,2922.27 ; v1@4684.73,3724.48 ccw(c4677.33,3735) 4690.19,3735 ccw(c4703.05,3735) v1@4695.65,3724.48 ; v1(4690.19,3716.71) 4690.19,3735 4680.52,3744.67 4680.52,3814.21 4737.18,3870.86 4860,3870.86 4870,3870.86 4936.73,3870.86 ; 4936.73,3870.86 ccw(c4936.73,3909.54) 4964.08,3882.19 ; 4936.73,3870.86 ccw(c4936.73,3909.54) 4964.08,3882.19 ; 4964.08,3882.19 cw(c4976.61,3869.66) 4976.61,3887.38 ccw(c4976.61,3869.66) 4964.08,3882.19 ; 4964.08,3882.19 ccw(c4951.55,3894.72) 4969.27,3894.72 cw(c4951.55,3894.72) 4964.08,3882.19
  Bottom Layer w4: v1@1259.29,2942.6 cw(c1249.59,2930.38) 1265.19,2930.38 ; v1(1265.19,2950.04) 1265.19,2930.37 ; v1@1271.1,2942.6 ccw(c1280.79,2930.38) 1265.19,2930.38 ; 1792.34,3145.54 1813.5,3166.7 1843.16,3166.7 1901.5,3225.04 2756.86,3225.04 2806.86,3175.04 4010,3175.04 4023.19,3188.23 4023.19,3210 4023.19,3266 4052.19,3295 4052.19,3315 4045.52,3321.67 4045.52,3470.35 4040.19,3475.69 4040.19,3516.71 4069.16,3545.68 ; 1796.8,3150 1727,3080.2 1727,2897 1707.87,2877.87 1501.78,2877.87 1487.95,2891.71 1303.86,2891.71 1265.19,2930.37 ; 4073.52,3550.04 4069.16,3545.68 ; v1(4690.19,3716.71) 4690.19,3684.35 4672.21,3666.37 4463.63,3666.37 4456.86,3673.14 4456.86,3703.14 4371.63,3788.37 4103.37,3788.37 4080,3765 4080,3556.52 4069.16,3545.68
PBIO.D27: EXTHDR1.56 U8.Y2 | length 6007.2
  Top Layer w4: EXTHDR1.56@1276.93,2904.37 cw(c1294.82,2904.37) 1282.17,2917.02 ; EXTHDR1.56@1278.2,2911.89 ccw(c1276.79,2915.78) 1280.93,2915.78 ; EXTHDR1.56@1280.93,2859.25 1280.93,2915.78 ; EXTHDR1.56@1280.93,2904.37 cw(c1308.47,2904.37) 1289,2923.85 ; EXTHDR1.56@1283.65,2911.89 cw(c1285.06,2915.78) 1280.93,2915.78 ; EXTHDR1.56@1284.93,2904.37 cw(c1322.13,2904.37) 1295.82,2930.68 ; 1285.26,2920.11 cw(c1320,2885.37) v1@1320,2934.5 ; EXTHDR1.56@1288.93,2904.37 cw(c1335.79,2904.37) 1302.65,2937.5 ; 1292.09,2926.94 cw(c1320,2899.03) v1@1320,2938.5 ; 1298.92,2933.77 cw(c1320,2912.68) v1@1320,2942.5 ; 1305.74,2940.6 cw(c1320,2926.34) v1@1320,2946.5 ; v1(1320,2940) 1308.56,2940 1306.86,2941.71 1280.93,2915.78 ; v1(4690.19,3883.37) 4711.82,3905 4765,3905 4778.59,3918.59 4851.26,3918.59 4855.26,3918.59 4860,3918.59 4870,3918.59 4917.53,3918.59 ; v1@4690.19,3888.87 ccw(c4690.19,3902.15) 4699.58,3892.76 ccw(c4708.97,3883.37) v1@4695.69,3883.37 ; v1@4690.19,3892.87 ccw(c4690.19,3915.81) 4706.41,3899.59 ccw(c4722.63,3883.37) v1@4699.69,3883.37 ; 4917.53,3918.59 ccw(c4917.53,3928.74) 4924.71,3921.56 ; 4917.53,3918.59 ccw(c4917.53,3928.74) 4924.71,3921.56 ; 4924.71,3921.56 ccw(c4912.17,3934.09) 4929.9,3934.09 cw(c4912.17,3934.09) 4924.71,3921.56 ; 4924.71,3921.56 cw(c4937.24,3909.03) 4937.24,3926.75 ccw(c4937.24,3909.03) 4924.71,3921.56
  Bottom Layer w4: v1(1320,2940) 1480,2940 1491,2951 1540,2951 1557,2968 1603.48,2968 1641.01,3005.53 1810.52,3175.04 1840.19,3175.04 1898.52,3233.37 2759.84,3233.37 2810.17,3183.04 4005,3183.04 4015.19,3193.23 4015.19,3268.19 4015.19,3315 4037.52,3337.33 4037.52,3467.04 4032.19,3472.37 4032.19,3512.81 3995,3550 3615.23,3550 3598.52,3566.71 3598.52,3766.71 3604.86,3773.04 4063.19,3773.04 4086.52,3796.37 4374.94,3796.37 4464.86,3706.46 4464.86,3680.14 4470.63,3674.37 4668.9,3674.37 4672.52,3678 4672.52,3865.71 v1(4690.19,3883.37) ; v1@1323.89,2936.11 cw(c1333.28,2926.72) 1333.28,2940 cw(c1333.28,2953.28) v1@1323.89,2943.89 ; v1@1326.72,2933.28 cw(c1342.93,2917.06) 1342.93,2940 cw(c1342.93,2962.93) v1@1326.72,2946.72 ; v1@4680.69,3883.37 cw(c4657.76,3883.37) 4673.97,3867.16 cw(c4690.19,3850.94) v1@4690.19,3873.87 ; v1@4684.69,3883.37 cw(c4671.41,3883.37) 4680.8,3873.99 cw(c4690.19,3864.6) v1@4690.19,3877.87
PBIO.D28: EXTHDR1.58 U8.Y1 | length 6912.8
  Top Layer w4: EXTHDR1.58@1249.43,2806.13 cw(c1249.43,2782.79) 1265.93,2799.3 ; EXTHDR1.58@1249.43,2810.13 cw(c1249.43,2796.45) 1259.11,2806.13 ; EXTHDR1.58@1249.43,2859.25 1249.43,2815.8 1265.19,2800.04 1265.19,2765 1206.86,2706.67 1206.86,2633.37 1206.86,2441.71 1265.19,2383.37 v1(1356.86,2383.37) ; EXTHDR1.58@1257.43,2814.13 ccw(c1272.72,2814.13) 1261.91,2803.32 ; v1@1350.14,2376.66 ccw(c1333.92,2360.44) 1333.92,2383.37 ccw(c1333.92,2406.31) v1@1350.14,2390.09 ; v1@1352.97,2379.49 ccw(c1343.58,2370.1) 1343.58,2383.37 ccw(c1343.58,2396.65) v1@1352.97,2387.26 ; v1@4473.84,3850.78 ccw(c4461.08,3865) 4480.19,3865 ccw(c4499.3,3865) v1@4486.54,3850.78 ; v1@4476.52,3847.8 ccw(c4469.13,3856.03) 4480.19,3856.03 ccw(c4491.25,3856.03) v1@4483.86,3847.8 ; v1(4480.19,3843.71) 4480.19,3865 4471.82,3873.37 4471.82,3940 4480.19,3948.37 4481.86,3950.04 4699.19,3950.04 4707.52,3941.71 4773.52,3941.71 4781.14,3934.09 4860,3934.09 4870,3934.09 U8.Y1@4897.87,3934.09 ; U8.Y1@4892.57,3928.79 ccw(c4879.77,3915.99) 4879.77,3934.09 ccw(c4879.77,3952.2) U8.Y1@4892.57,3939.4 ; 4880.15,3934.09 cw(c4880.15,3916.37) 4892.68,3928.9 ccw(c4880.15,3916.37) 4880.15,3934.09 ; 4880.15,3934.09 ccw(c4880.15,3951.82) 4892.68,3939.29 cw(c4880.15,3951.82) 4880.15,3934.09
  MidLayer1 w4: v1@1356.86,2373.87 cw(c1356.86,2350.94) 1373.07,2367.16 cw(c1389.29,2383.37) v1@1366.36,2383.37 ; v1@1356.86,2377.87 cw(c1356.86,2364.6) 1366.25,2373.99 cw(c1375.64,2383.37) v1@1362.36,2383.37 ; v1(1356.86,2383.37) 1377,2363.23 1377,1904.9 1400.9,1881 1911.63,1881 1951.63,1841 1993.34,1841 2017.63,1816.71 2080,1816.71 2113.29,1850 2395.5,1850 2473.86,1928.35 2473.86,2322.54 2501.81,2350.5 3082.32,2350.5 3631.86,2900.04 3631.86,3541.71 3640.19,3550.04 4065.19,3550.04 4073.52,3558.37 4073.52,3773.37 4056.19,3790.71 v1(4031.86,3790.71) ; v1@4035.75,3786.82 cw(c4045.14,3777.43) 4045.14,3790.71 cw(c4045.14,3803.99) v1@4035.75,3794.6 ; v1@4038.57,3783.99 cw(c4054.79,3767.77) 4054.79,3790.71 cw(c4054.79,3813.64) v1@4038.57,3797.43
  Bottom Layer w4: v1(4031.86,3790.71) 4069.54,3790.71 4083.21,3804.37 4378.25,3804.37 4391.92,3790.71 4427.19,3790.71 v1(4480.19,3843.71) ; v1@4035.75,3786.82 cw(c4045.14,3777.43) 4045.14,3790.71 cw(c4045.14,3803.99) v1@4035.75,3794.6 ; v1@4038.57,3783.99 cw(c4054.79,3767.77) 4054.79,3790.71 cw(c4054.79,3813.64) v1@4038.57,3797.43 ; v1@4470.69,3843.71 cw(c4447.76,3843.71) 4463.97,3827.49 cw(c4480.19,3811.27) v1@4480.19,3834.21 ; v1@4474.69,3843.71 cw(c4461.41,3843.71) 4470.8,3834.32 cw(c4480.19,3824.93) v1@4480.19,3838.21
PBIO.D29: EXTHDR1.60 U8.W3 | length 5840.5
  Top Layer w4: EXTHDR1.60@1217.94,2806.13 cw(c1217.94,2795.28) 1225.61,2802.95 ; EXTHDR1.60@1217.94,2859.25 1217.94,2810.63 v1(1240.19,2788.37) ; EXTHDR1.60@1221.94,2814.13 ccw(c1240.05,2814.13) 1227.24,2801.32 ; EXTHDR1.60@1225.94,2814.13 ccw(c1253.71,2814.13) v1@1234.07,2794.5 ; v1@1230.69,2788.37 ccw(c1207.76,2788.37) 1223.97,2804.59 ccw(c1240.19,2820.81) v1@1240.19,2797.87 ; v1@1234.69,2788.37 ccw(c1221.41,2788.37) 1230.8,2797.76 ccw(c1240.19,2807.15) v1@1240.19,2793.87 ; v1@4698.52,2897.21 ccw(c4698.52,2910.49) 4707.91,2901.1 ccw(c4717.3,2891.71) v1@4704.02,2891.71 ; v1@4698.52,2901.21 ccw(c4698.52,2924.14) 4714.74,2907.93 ccw(c4730.96,2891.71) v1@4708.02,2891.71 ; v1@4706.86,2891.71 v1(4698.52,2891.71) 4721.26,2914.45 4759.95,2914.45 4790.19,2944.69 4790.19,3141.71 4773.52,3158.37 4740.19,3158.37 4723.52,3175.04 4723.52,3225.04 4731.19,3232.71 4731.19,3325.71 4723.52,3333.37 4723.52,3363.73 4703.54,3383.71 4681.52,3383.71 ; U8.W3@4969.27,3973.46 cw(c4951.55,3973.46) 4964.08,3960.93 ; U8.W3@4976.61,3966.12 ccw(c4976.61,3948.4) 4964.08,3960.93 ; 4665.19,3400.04 4675.19,3390.04 ; 4665.19,3400.04 4675.19,3390.04 ; 4665.19,3400.04 4665.19,3658.37 4648.52,3675.04 4490.19,3675.04 4481.86,3683.37 4481.86,3778.63 4462.52,3797.96 4462.52,3942.37 4478.52,3958.37 4702.19,3958.37 4710.86,3949.71 4776.84,3949.71 4776.94,3949.6 4851.26,3949.6 4855.26,3949.6 4860,3949.6 4870,3949.6 4936.73,3949.6 ccw(c4936.73,3988.28) 4964.08,3960.93 ; 4675.19,3390.04 4681.52,3383.71 ; 4675.19,3390.04 4681.52,3383.71
  MidLayer2 w4: v1(1240.19,2788.37) 1240.19,2791.71 1256.86,2808.37 ; v1@1240.19,2797.87 ccw(c1240.19,2812.76) 1250.72,2802.24 ; v1@1245.68,2788.77 cw(c1262.84,2790.02) 1250.67,2802.19 ; v1@1249.67,2789.06 cw(c1274.37,2790.86) 1256.86,2808.37 ; v1@4691.81,2884.99 ccw(c4675.59,2868.77) 4675.59,2891.71 ccw(c4675.59,2914.64) v1@4691.81,2898.43 ; v1@4694.64,2887.82 ccw(c4685.25,2878.43) 4685.25,2891.71 ccw(c4685.25,2904.99) v1@4694.64,2895.6 ; v1(4698.52,2891.71) 4323.96,2891.71 4273.63,2841.37 3319.54,2841.37 3236.21,2758.04 3005.33,2758.04 2980,2783.37 2150,2783.37 2128.88,2783.37 1975,2783.37 1950,2808.37 1256.86,2808.37
PBIO.D30: EXTHDR1.62 U8.W4 | length 5019.4
  Top Layer w4: v1(1173.52,2975.04) 1173.52,2960.67 1189.19,2945 1189.19,2917.71 1190.19,2916.71 ; EXTHDR1.62@1186.05,2912.36 ccw(c1185.84,2916.71) 1190.19,2916.71 ; EXTHDR1.62@1190.19,2883.37 1190.19,2916.71 ; 1190.19,2914.63 ccw(c1196.7,2914.63) EXTHDR1.62@1192.1,2910.03 ; v3(4996.3,3953.78) U8.W4@5015.98,3973.46 ; U8.W4@5008.48,3973.46 cw(c4990.38,3973.46) 5003.18,3960.66 cw(c5015.98,3947.86) U8.W4@5015.98,3965.96 ; U8.W4@5008.64,3973.46 cw(c4990.92,3973.46) 5003.45,3960.93 cw(c5015.98,3948.4) U8.W4@5015.98,3966.12 ; 5009.1,3966.58 ccw(c5021.91,3953.78) 5003.8,3953.78 cw(c5021.91,3953.78) 5009.1,3966.58 ; 5009.1,3966.58 cw(c4996.3,3979.39) 4996.3,3961.28 ccw(c4996.3,3979.39) 5009.1,3966.58
  MidLayer1 w4: v1@4697.36,3632.37 ccw(c4674.42,3632.37) 4690.64,3648.59 ccw(c4706.86,3664.81) v1@4706.86,3641.87 ; v1@4701.36,3632.37 ccw(c4688.08,3632.37) 4697.47,3641.76 ccw(c4706.86,3651.15) v1@4706.86,3637.87 ; v1(4706.86,3632.37) 4690.19,3649.04 4690.19,3691.71 4698.52,3700.04 4731.86,3700.04 4754.19,3722.37 4754.19,3782.12 4731.19,3805.12 4731.19,3939.88 4733.02,3941.71 4755,3941.71 4767.07,3953.78 4860,3953.78 4870,3953.78 4918.62,3953.78 v3(4996.3,3953.78) ; v3@4991,3948.48 ccw(c4978.19,3935.67) 4978.19,3953.78 ccw(c4978.19,3971.89) v3@4991,3959.08 ; v3@4991.11,3948.59 ccw(c4978.57,3936.05) 4978.57,3953.78 ccw(c4978.57,3971.51) v3@4991.11,3958.97
  MidLayer2 w4: v1(1173.52,2975.04) 1390.19,3191.71 1659.71,3191.71 1685,3217 1721.69,3217 1746.98,3191.71 1850,3191.71 1891.67,3233.37 2178,3233.37 2723.52,3233.37 2798.52,3308.37 3756.86,3308.37 3773.52,3325.04 4006.86,3325.04 4048.52,3366.71 4099.5,3366.71 4122.4,3389.61 4123.52,3390.73 4123.52,3425.04 4181.86,3483.37 4498.52,3483.37 4565.19,3550.04 4615.19,3550.04 4706.86,3641.71 v1(4706.86,3632.37) ; v1@1173.52,2980.54 ccw(c1173.52,2993.82) 1182.91,2984.43 ccw(c1192.3,2975.04) v1@1179.02,2975.04 ; v1@1173.52,2984.54 ccw(c1173.52,3007.48) 1189.74,2991.26 ccw(c1205.96,2975.04) v1@1183.02,2975.04 ; 4674.71,3609.56 cw(c4706.86,3577.41) v1@4706.86,3622.87 ; 4681.54,3616.39 cw(c4706.86,3591.06) v1@4706.86,3626.87 ; 4688.36,3623.21 cw(c4706.86,3604.72) v1@4706.86,3630.87 ; 4695.19,3630.04 cw(c4706.86,3618.38) v1@4706.86,3634.87
PBIO.D31: EXTHDR1.64 U8.V6 | length 5307.2
  Top Layer w4: 1148.52,2917.28 ccw(c1164.72,2917.28) 1154.94,2904.37 1148.52,2904.36 1148.52,2933.37 ; 1148.52,2925.33 ccw(c1170.81,2925.33) EXTHDR1.64@1157.36,2907.56 ; 1148.69,2933.54 cw(c1158.27,2923.96) v1@1163.19,2936.58 ; 1153.02,2937.87 cw(c1160.7,2930.19) v1@1164.65,2940.31 ; EXTHDR1.64@1154.94,2859.25 EXTHDR1.64@1154.95,2904.36 ; EXTHDR1.64@1159.77,2910.75 cw(c1176.91,2933.37) 1148.52,2933.37 ; v1(1165.19,2941.71) 1156.86,2941.71 1148.52,2933.37 ; v3(5075.04,3993.15) U8.V6@5094.72,4012.83 ; v3@5082.54,3993.15 cw(c5100.65,3993.15) 5087.84,4005.95 ; v3@5082.54,3993.15 cw(c5100.65,3993.15) 5087.84,4005.95 ; U8.V6@5087.22,4012.83 cw(c5069.12,4012.83) 5081.92,4000.03 cw(c5094.72,3987.23) U8.V6@5094.72,4005.33 ; U8.V6@5087.38,4012.83 cw(c5069.66,4012.83) 5082.19,4000.3 cw(c5094.72,3987.77) U8.V6@5094.72,4005.49 ; 5087.84,4005.95 cw(c5075.04,4018.76) 5075.04,4000.65 ccw(c5075.04,4018.76) 5087.84,4005.95
  MidLayer1 w4: v1@4726.14,3773.43 ccw(c4709.92,3789.64) 4732.86,3789.64 ccw(c4755.79,3789.64) v1@4739.57,3773.43 ; v1@4728.97,3770.6 ccw(c4719.58,3779.99) 4732.86,3779.99 ccw(c4746.14,3779.99) v1@4736.75,3770.6 ; v1(4732.86,3766.71) 4732.86,3792.14 4723.19,3801.81 4723.19,3943.19 4730.04,3950.04 4752.02,3950.04 4771.27,3969.29 4860,3969.29 4870,3969.29 4918.62,3969.29 4938.04,3969.29 5012.16,3969.29 ; 4998.23,3969.29 5012.16,3969.29 ; v3@5067.57,3993.8 cw(c5049.53,3995.38) 5061.17,3981.51 ; v3@5074.39,3985.68 ccw(c5072.81,3967.64) 5061.17,3981.51 ; 5012.16,3969.29 5031.66,3969.29 ccw(c5031.66,4011.02) 5061.17,3981.51
  MidLayer2 w4: v1(1165.19,2941.71) 1215.19,2991.71 1215.19,3001.16 1389.07,3175.04 1675.96,3175.04 1697,3154 1735.82,3154 1765.19,3183.37 1852.98,3183.37 1894.98,3225.37 2766.33,3225.37 2775,3216.71 2973.52,3216.71 3031.86,3275.04 3090.19,3275.04 3132.19,3233.04 3286.21,3233.04 3328.21,3275.04 4087.21,3275.04 4162.09,3349.92 4175,3362.83 4175,3460 4190.04,3475.04 4440.19,3475.04 4456.86,3458.37 4456.86,3450.04 4467.52,3439.37 4506.86,3439.37 4575.86,3508.37 4588.37,3508.37 4690,3610 4735,3610 4790.19,3665.19 4790.19,3750.04 4773.52,3766.71 v1(4732.86,3766.71) ; v1@1165.19,2947.21 ccw(c1165.19,2960.49) 1174.58,2951.1 ccw(c1183.97,2941.71) v1@1170.69,2941.71 ; v1@1165.19,2951.21 ccw(c1165.19,2974.14) 1181.41,2957.93 ccw(c1197.63,2941.71) v1@1174.69,2941.71 ; v1@4736.75,3762.82 cw(c4746.14,3753.43) 4746.14,3766.71 cw(c4746.14,3779.99) v1@4736.75,3770.6 ; v1@4739.57,3759.99 cw(c4755.79,3743.77) 4755.79,3766.71 cw(c4755.79,3789.64) v1@4739.57,3773.43
PBIO.D32: EXTHDR1.66 U8.V7 | length 8892.8
  Top Layer w4: EXTHDR1.66@1117.79,2808.48 cw(c1104.13,2794.82) 1123.45,2794.82 cw(c1142.76,2794.82) EXTHDR1.66@1129.1,2808.48 ; EXTHDR1.66@1123.45,2859.25 1123.45,2425.12 1165.19,2383.37 v1(1165.19,2150.04) ; v1@1158.47,2156.76 ccw(c1142.26,2172.98) 1165.19,2172.98 ccw(c1188.13,2172.98) v1@1171.91,2156.76 ; v1@1161.3,2153.93 ccw(c1151.91,2163.32) 1165.19,2163.32 ccw(c1178.47,2163.32) v1@1169.08,2153.93 ; v1@2408.47,3347.99 cw(c2392.26,3331.77) 2415.19,3331.77 cw(c2438.13,3331.77) v1@2421.91,3347.99 ; v1@2411.3,3350.82 cw(c2401.91,3341.43) 2415.19,3341.43 cw(c2428.47,3341.43) v1@2419.08,3350.82 ; v1(2415.19,3354.71) 2415.19,3211.36 3005.69,2620.86 3034.14,2620.86 3040.19,2614.81 v1(3040.19,2600.04) ; v3(5114.41,3993.15) U8.V7@5134.09,4012.83 ; v3@5121.91,3993.15 cw(c5140.02,3993.15) 5127.21,4005.95 ; v3@5121.91,3993.15 cw(c5140.02,3993.15) 5127.21,4005.95 ; U8.V7@5126.59,4012.83 cw(c5108.49,4012.83) 5121.29,4000.03 cw(c5134.09,3987.23) U8.V7@5134.09,4005.33 ; U8.V7@5126.75,4012.83 cw(c5109.03,4012.83) 5121.56,4000.3 cw(c5134.09,3987.77) U8.V7@5134.09,4005.49 ; 5127.21,4005.95 cw(c5114.41,4018.76) 5114.41,4000.65 ccw(c5114.41,4018.76) 5127.21,4005.95
  MidLayer1 w4: v1@1790.19,2140.54 cw(c1790.19,2117.61) 1806.41,2133.82 cw(c1822.63,2150.04) v1@1799.69,2150.04 ; v1@1790.19,2144.54 cw(c1790.19,2131.26) 1799.58,2140.65 cw(c1808.97,2150.04) v1@1795.69,2150.04 ; v1(1790.19,2150.04) 1812.23,2128 1918.31,2128 1938,2108.31 1938,1913.55 1978.55,1873 2018.25,1873 2027.75,1882.5 2042.25,1882.5 2064.75,1860 2394.19,1860 2465.86,1931.67 2465.86,2325.86 2498.5,2358.5 3043.5,2358.5 v1(3065,2380) ; v1@3055.5,2380 cw(c3032.56,2380) 3048.78,2363.78 cw(c3065,2347.56) v1@3065,2370.5 ; v1@3059.5,2380 cw(c3046.22,2380) 3055.61,2370.61 cw(c3065,2361.22) v1@3065,2374.5
  MidLayer2 w4: v1(1165.19,2150.04) 1190,2150.04 1195,2155.04 1195,2223.69 1247.69,2276.37 1406,2276.37 1478.37,2204 1542.55,2204 1598.55,2260 1650.04,2260 1760,2150.04 v1(1790.19,2150.04) ; v1@1169.08,2146.15 cw(c1178.47,2136.76) 1178.47,2150.04 cw(c1178.47,2163.32) v1@1169.08,2153.93 ; v1@1171.91,2143.32 cw(c1188.13,2127.11) 1188.13,2150.04 cw(c1188.13,2172.98) v1@1171.91,2156.76 ; v1@1783.47,2143.32 ccw(c1767.26,2127.11) 1767.26,2150.04 ccw(c1767.26,2172.98) v1@1783.47,2156.76 ; v1@1786.3,2146.15 ccw(c1776.91,2136.76) 1776.91,2150.04 ccw(c1776.91,2163.32) v1@1786.3,2153.93 ; v1(2415.19,3354.71) 2603.19,3354.71 2623.52,3375.04 2623.52,3525.04 2648.52,3550.04 2898.52,3550.04 2931.86,3583.37 2931.86,3641.71 2948.52,3658.37 3405,3658.37 3431.52,3684.9 3431.52,4045.21 3448.31,4062 3622,4062 3660.71,4100.71 4061.54,4100.71 4112.21,4050.04 4298.52,4050.04 4404.52,3944.04 4442.52,3944.04 4456.86,3958.37 4693.17,3958.37 4701.55,3950 4762.78,3950 4790.42,3977.64 4860,3977.64 4870,3977.64 4997.36,3977.64 5090.9,3977.64 ccw(c5090.9,3991.69) 5100.83,3981.76 ; v1@2419.08,3350.82 cw(c2428.47,3341.43) 2428.47,3354.71 cw(c2428.47,3367.99) v1@2419.08,3358.6 ; v1@2421.91,3347.99 cw(c2438.13,3331.77) 2438.13,3354.71 cw(c2438.13,3377.64) v1@2421.91,3361.43 ; v3@5106.94,3993.8 cw(c5088.9,3995.38) 5100.54,3981.51 cw(c5112.18,3967.64) v3@5113.76,3985.68
  Bottom Layer w4: v1@3033.47,2593.32 cw(c3017.26,2577.11) 3040.19,2577.11 cw(c3063.13,2577.11) v1@3046.91,2593.32 ; v1@3036.3,2596.15 cw(c3026.91,2586.76) 3040.19,2586.76 cw(c3053.47,2586.76) v1@3044.08,2596.15 ; v1(3040.19,2600.04) 3040.19,2404.81 v1(3065,2380) ; v1@3055.5,2380 ccw(c3032.56,2380) 3048.78,2396.22 ccw(c3065,2412.43) v1@3065,2389.5 ; v1@3059.5,2380 ccw(c3046.22,2380) 3055.61,2389.39 ccw(c3065,2398.78) v1@3065,2385.5
PBIO.D33: EXTHDR1.68 U8.U8 | length 6466.8
  Top Layer w4: v1@1083.47,2731.76 ccw(c1067.26,2747.98) 1090.19,2747.98 ccw(c1113.13,2747.98) v1@1096.91,2731.76 ; EXTHDR1.68@1086.29,2808.48 cw(c1072.64,2794.82) 1091.95,2794.82 cw(c1111.27,2794.82) EXTHDR1.68@1097.61,2808.48 ; v1@1086.3,2728.93 ccw(c1076.91,2738.32) 1090.19,2738.32 ccw(c1103.47,2738.32) v1@1094.08,2728.93 ; v1(1090.19,2725.04) 1090.19,2758.37 1098.52,2766.71 1098.52,2780 1091.95,2786.57 EXTHDR1.68@1091.95,2859.25 ; v3(5153.78,4032.52) U8.U8@5173.46,4052.2 ; U8.U8@5165.96,4052.2 cw(c5147.86,4052.2) 5160.66,4039.4 cw(c5173.46,4026.6) U8.U8@5173.46,4044.7 ; U8.U8@5166.12,4052.2 cw(c5148.4,4052.2) 5160.93,4039.67 cw(c5173.46,4027.14) U8.U8@5173.46,4044.86 ; 5166.58,4045.32 cw(c5153.78,4058.13) 5153.78,4040.02 ccw(c5153.78,4058.13) 5166.58,4045.32 ; 5166.58,4045.32 ccw(c5179.39,4032.52) 5161.28,4032.52 cw(c5179.39,4032.52) 5166.58,4045.32
  MidLayer1 w4: v1(3481.86,2583.37) 3594.94,2583.37 3660,2648.44 3660,2735.75 3690.19,2765.94 v1(3690.19,3350.04) ; v1@3485.75,2579.49 cw(c3495.14,2570.1) 3495.14,2583.37 cw(c3495.14,2596.65) v1@3485.75,2587.26 ; v1@3488.57,2576.66 cw(c3504.79,2560.44) 3504.79,2583.37 cw(c3504.79,2606.31) v1@3488.57,2590.09 ; v1@3683.47,3343.32 cw(c3667.26,3327.11) 3690.19,3327.11 cw(c3713.13,3327.11) v1@3696.91,3343.32 ; v1@3686.3,3346.15 cw(c3676.91,3336.76) 3690.19,3336.76 cw(c3703.47,3336.76) v1@3694.08,3346.15
  MidLayer2 w4: v1(1090.19,2725.04) 1939.96,2725.04 2097,2568 3052.96,2568 3093.67,2608.71 3456.52,2608.71 v1(3481.86,2583.37) ; v1@1094.08,2721.15 cw(c1103.47,2711.76) 1103.47,2725.04 cw(c1103.47,2738.32) v1@1094.08,2728.93 ; v1@1096.91,2718.32 cw(c1113.13,2702.11) 1113.13,2725.04 cw(c1113.13,2747.98) v1@1096.91,2731.76 ; v1@3472.36,2583.37 ccw(c3449.42,2583.37) 3465.64,2599.59 ccw(c3481.86,2615.81) v1@3481.86,2592.87 ; v1@3476.36,2583.37 ccw(c3463.08,2583.37) 3472.47,2592.76 ccw(c3481.86,2602.15) v1@3481.86,2588.87 ; v1@4448.52,4031.21 cw(c4448.52,4008.27) 4464.74,4024.49 cw(c4480.96,4040.71) v1@4458.02,4040.71 ; v1@4448.52,4035.21 cw(c4448.52,4021.93) 4457.91,4031.32 cw(c4467.3,4040.71) v1@4454.02,4040.71 ; v1(4448.52,4040.71) 4471.52,4017.71 4645.15,4017.71 4704.48,3958.37 4759.84,3958.37 4810.12,4008.66 4860,4008.66 4870,4008.66 4997.36,4008.66 5016.78,4008.66 5090.9,4008.66 5110.4,4008.66 ccw(c5110.4,4050.39) 5139.91,4020.88 ; v3@5146.31,4033.17 cw(c5128.27,4034.75) 5139.91,4020.88 ; v3@5153.13,4025.05 ccw(c5151.55,4007.01) 5139.91,4020.88
  Bottom Layer w4: v1@3683.47,3343.32 ccw(c3667.26,3327.11) 3667.26,3350.04 ccw(c3667.26,3372.98) v1@3683.47,3356.76 ; v1@3686.3,3346.15 ccw(c3676.91,3336.76) 3676.91,3350.04 ccw(c3676.91,3363.32) v1@3686.3,3353.93 ; v1(3690.19,3350.04) 3648.52,3350.04 3631.86,3366.71 3631.86,3405.37 3573.52,3463.71 3573.52,3836.36 3620.21,3883.04 3939.67,3883.04 4028.67,3972.04 4348.52,3972.04 4409.25,4032.77 4417.19,4040.71 v1(4448.52,4040.71) ; v1@4441.81,4033.99 ccw(c4425.59,4017.77) 4425.59,4040.71 ccw(c4425.59,4063.64) v1@4441.81,4047.43 ; v1@4444.64,4036.82 ccw(c4435.25,4027.43) 4435.25,4040.71 ccw(c4435.25,4053.99) v1@4444.64,4044.6
PBIO.D34: EXTHDR1.70 U8.U9 | length 6069.2
  Top Layer w4: EXTHDR1.70@1054.8,2808.48 cw(c1041.14,2794.82) 1060.46,2794.82 cw(c1079.77,2794.82) EXTHDR1.70@1066.11,2808.48 ; EXTHDR1.70@1060.46,2866.71 EXTHDR1.70@1060.46,2859.25 1060.46,2792.78 v1(1073.52,2779.71) ; v3(5193.15,4032.52) U8.U9@5212.83,4052.2 ; U8.U9@5205.33,4052.2 cw(c5187.23,4052.2) 5200.03,4039.4 cw(c5212.83,4026.6) U8.U9@5212.83,4044.7 ; U8.U9@5205.49,4052.2 cw(c5187.77,4052.2) 5200.3,4039.67 cw(c5212.83,4027.14) U8.U9@5212.83,4044.86 ; 5205.95,4045.32 cw(c5193.15,4058.13) 5193.15,4040.02 ccw(c5193.15,4058.13) 5205.95,4045.32 ; 5205.95,4045.32 ccw(c5218.76,4032.52) 5200.65,4032.52 cw(c5218.76,4032.52) 5205.95,4045.32
  MidLayer1 w4: v1@4200.14,2798.43 ccw(c4183.92,2814.64) 4206.86,2814.64 ccw(c4229.79,2814.64) v1@4213.57,2798.43 ; v1@4202.97,2795.6 ccw(c4193.58,2804.99) 4206.86,2804.99 ccw(c4220.14,2804.99) v1@4210.75,2795.6 ; v1(4206.86,2791.71) 4206.86,2946.71 4373.52,3113.37 4373.52,3225.04 4348.84,3249.72 4343.09,3249.72 4304.52,3288.29 4304.52,3714.52 4323.37,3733.37 4381.86,3733.37 4401.86,3753.37 v1(4401.86,3808.37) ; v1@4395.14,3801.66 cw(c4378.92,3785.44) 4401.86,3785.44 cw(c4424.79,3785.44) v1@4408.57,3801.66 ; v1@4397.97,3804.49 cw(c4388.58,3795.1) 4401.86,3795.1 cw(c4415.14,3795.1) v1@4405.75,3804.49
  MidLayer2 w4: v1(1073.52,2779.71) 1118.86,2779.71 1165.19,2733.37 1959.31,2733.37 1985.31,2759.37 2969.71,2759.37 2995.04,2734.04 3139.65,2734.04 3194.65,2679.04 3580,2679.04 3676,2775.04 4165.19,2775.04 4181.86,2791.71 v1(4206.86,2791.71) ; v1@1077.41,2775.82 cw(c1086.8,2766.43) 1086.8,2779.71 cw(c1086.8,2792.99) v1@1077.41,2783.6 ; v1@1080.24,2772.99 cw(c1096.46,2756.77) 1096.46,2779.71 cw(c1096.46,2802.64) v1@1080.24,2786.43 ; v1@4200.14,2784.99 ccw(c4183.92,2768.77) 4183.92,2791.71 ccw(c4183.92,2814.64) v1@4200.14,2798.43 ; v1@4202.97,2787.82 ccw(c4193.58,2778.43) 4193.58,2791.71 ccw(c4193.58,2804.99) v1@4202.97,2795.6
  Bottom Layer w4: v1@4401.86,3805.87 ccw(c4401.86,3823.52) 4414.34,3811.04 ; v1(4401.86,3808.37) 4411.67,3808.37 4470,3866.71 4481.52,3866.71 4489.86,3875.04 4489.86,3948.37 4491.52,3950.04 4666.86,3950.04 4668.52,3948.37 4670,3946.9 4670,3915.23 4680.23,3905 4803.48,3905 4815.19,3916.71 4815.19,4000.04 4831.86,4016.71 4851.26,4016.71 4851.26,4017.01 4855.26,4017.01 4860,4017.01 4870,4017.01 5076.1,4017.01 5169.64,4017.01 ccw(c5169.64,4031.06) 5179.57,4021.13 ; v1@4401.86,3809.87 ccw(c4401.86,3837.18) 4421.16,3817.87 ; v1@4401.86,3813.87 ccw(c4401.86,3850.84) 4427.99,3824.7 ; v1@4401.86,3817.87 ccw(c4401.86,3864.49) 4434.82,3831.53 ; v3@5185.68,4033.17 cw(c5167.64,4034.75) 5179.28,4020.88 cw(c5190.92,4007.01) v3@5192.5,4025.05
